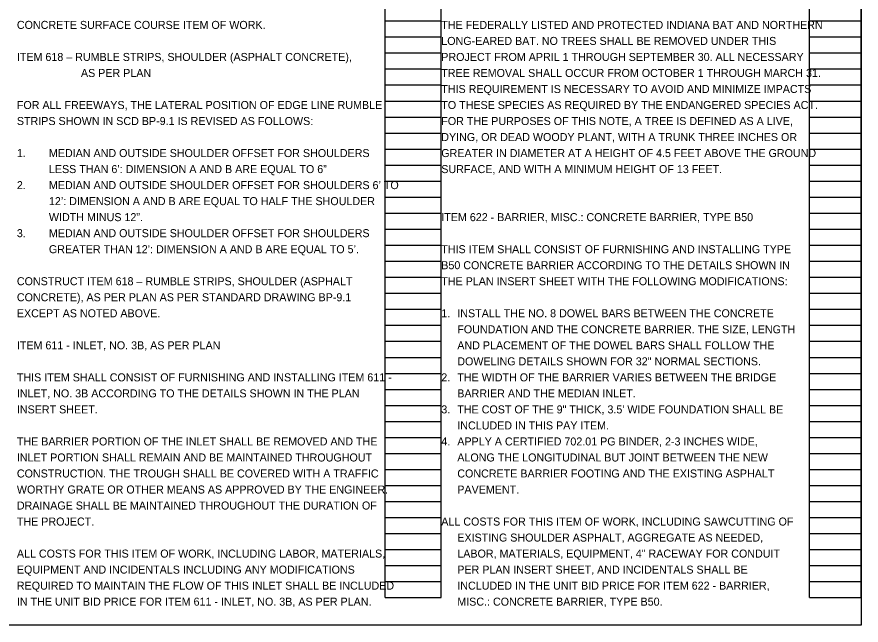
# Model space of a CAD drawing. Extents: x 0 to 2132911, y 0 to 658646.
# Drawn here: x 17.24 to 32, y 0.5 to 11.13 of the extents above; entities that cross this region are included whole.
import ezdxf

# ---------------------------------------------------------------- set-up
doc = ezdxf.new("R2010")
doc.units = 0
for name, color, linetype in [('SC_Scratch1', 7, 'Continuous'), ('SH_Data', 7, 'Continuous'), ('SH_Text', 7, 'Continuous')]:
    doc.layers.add(name, color=color, linetype=linetype)

msp = doc.modelspace()

# ---------------------------------------------------------------- linework, layer by layer
at = {"layer": 'SC_Scratch1'}
msp.add_lwpolyline([(1.5, 21.5), (32, 21.5), (32, 0.5), (1.5, 0.5)], close=True, dxfattribs=at)
at = {"layer": 'SH_Data'}
for p, q in [((23.68, 0.98), (23.68, 21.14)), ((24.66, 0.98), (24.66, 21.14)), ((31.1, 0.98), (31.1, 21.14)), ((32, 0.98), (32, 21.14)), ((23.68, 11.06), (24.66, 11.06)), ((31.1, 11.06), (32, 11.06)), ((23.68, 10.78), (24.66, 10.78)), ((31.1, 10.78), (32, 10.78)), ((23.68, 10.5), (24.66, 10.5)), ((31.1, 10.5), (32, 10.5)), ((23.68, 10.22), (24.66, 10.22)), ((31.1, 10.22), (32, 10.22)), ((23.68, 9.94), (24.66, 9.94)), ((31.1, 9.94), (32, 9.94)), ((23.68, 9.66), (24.66, 9.66)), ((31.1, 9.66), (32, 9.66)), ((23.68, 9.38), (24.66, 9.38)), ((31.1, 9.38), (32, 9.38)), ((23.68, 9.1), (24.66, 9.1)), ((31.1, 9.1), (32, 9.1)), ((23.68, 8.82), (24.66, 8.82)), ((31.1, 8.82), (32, 8.82)), ((23.68, 8.54), (24.66, 8.54)), ((31.1, 8.54), (32, 8.54)), ((23.68, 8.26), (24.66, 8.26)), ((31.1, 8.26), (32, 8.26)), ((23.68, 7.98), (24.66, 7.98)), ((31.1, 7.98), (32, 7.98)), ((23.68, 7.7), (24.66, 7.7)), ((31.1, 7.7), (32, 7.7)), ((23.68, 7.42), (24.66, 7.42)), ((31.1, 7.42), (32, 7.42)), ((23.68, 7.14), (24.66, 7.14)), ((31.1, 7.14), (32, 7.14)), ((23.68, 6.86), (24.66, 6.86)), ((31.1, 6.86), (32, 6.86)), ((23.68, 6.58), (24.66, 6.58)), ((31.1, 6.58), (32, 6.58)), ((23.68, 6.3), (24.66, 6.3)), ((31.1, 6.3), (32, 6.3)), ((23.68, 6.02), (24.66, 6.02)), ((31.1, 6.02), (32, 6.02)), ((23.68, 5.74), (24.66, 5.74)), ((31.1, 5.74), (32, 5.74)), ((23.68, 5.46), (24.66, 5.46)), ((31.1, 5.46), (32, 5.46)), ((23.68, 5.18), (24.66, 5.18)), ((31.1, 5.18), (32, 5.18)), ((23.68, 4.9), (24.66, 4.9)), ((31.1, 4.9), (32, 4.9)), ((23.68, 4.62), (24.66, 4.62)), ((31.1, 4.62), (32, 4.62)), ((23.68, 4.34), (24.66, 4.34)), ((31.1, 4.34), (32, 4.34)), ((23.68, 4.06), (24.66, 4.06)), ((31.1, 4.06), (32, 4.06)), ((23.68, 3.78), (24.66, 3.78)), ((31.1, 3.78), (32, 3.78)), ((23.68, 3.5), (24.66, 3.5)), ((31.1, 3.5), (32, 3.5)), ((23.68, 3.22), (24.66, 3.22)), ((31.1, 3.22), (32, 3.22)), ((23.68, 2.94), (24.66, 2.94)), ((31.1, 2.94), (32, 2.94)), ((23.68, 2.66), (24.66, 2.66)), ((31.1, 2.66), (32, 2.66)), ((23.68, 2.38), (24.66, 2.38)), ((31.1, 2.38), (32, 2.38)), ((23.68, 2.1), (24.66, 2.1)), ((31.1, 2.1), (32, 2.1)), ((23.68, 1.82), (24.66, 1.82)), ((31.1, 1.82), (32, 1.82)), ((23.68, 1.54), (24.66, 1.54)), ((31.1, 1.54), (32, 1.54)), ((23.68, 1.26), (24.66, 1.26)), ((31.1, 1.26), (32, 1.26)), ((23.68, 0.98), (24.66, 0.98)), ((31.1, 0.98), (32, 0.98))]:
    msp.add_line(p, q, dxfattribs=at)

# ---------------------------------------------------------------- texts
at = {"layer": 'SH_Text'}
for s, p in [('CONCRETE SURFACE COURSE ITEM OF WORK.', (17.24, 10.92)), ('THE FEDERALLY LISTED AND PROTECTED INDIANA BAT AND NORTHERN ', (24.66, 10.92)), ('LONG-EARED BAT. NO TREES SHALL BE REMOVED UNDER THIS ', (24.66, 10.64)), ('ITEM 618 – RUMBLE STRIPS, SHOULDER (ASPHALT CONCRETE),', (17.24, 10.36)), ('PROJECT FROM APRIL 1 THROUGH SEPTEMBER 30. ALL NECESSARY ', (24.66, 10.36)), ('AS PER PLAN', (18.36, 10.08)), ('TREE REMOVAL SHALL OCCUR FROM OCTOBER 1 THROUGH MARCH 31. ', (24.66, 10.08)), ('THIS REQUIREMENT IS NECESSARY TO AVOID AND MINIMIZE IMPACTS ', (24.66, 9.8)), ('FOR ALL FREEWAYS, THE LATERAL POSITION OF EDGE LINE RUMBLE ', (17.24, 9.52)), ('TO THESE SPECIES AS REQUIRED BY THE ENDANGERED SPECIES ACT. ', (24.66, 9.52)), ('STRIPS SHOWN IN SCD BP-9.1 IS REVISED AS FOLLOWS:', (17.24, 9.24)), ('FOR THE PURPOSES OF THIS NOTE, A TREE IS DEFINED AS A LIVE, ', (24.66, 9.24)), ('DYING, OR DEAD WOODY PLANT, WITH A TRUNK THREE INCHES OR ', (24.66, 8.96)), ('1.', (17.24, 8.68)), ('MEDIAN AND OUTSIDE SHOULDER OFFSET FOR SHOULDERS ', (17.8, 8.68)), ('GREATER IN DIAMETER AT A HEIGHT OF 4.5 FEET ABOVE THE GROUND ', (24.66, 8.68)), ('LESS THAN 6’: DIMENSION A AND B ARE EQUAL TO 6”', (17.8, 8.4)), ('SURFACE, AND WITH A MINIMUM HEIGHT OF 13 FEET.', (24.66, 8.4)), ('2.', (17.24, 8.12)), ('MEDIAN AND OUTSIDE SHOULDER OFFSET FOR SHOULDERS 6’ TO ', (17.8, 8.12)), ('12’: DIMENSION A AND B ARE EQUAL TO HALF THE SHOULDER ', (17.8, 7.84)), ('WIDTH MINUS 12”.', (17.8, 7.56)), ('ITEM 622 - BARRIER, MISC.: CONCRETE BARRIER, TYPE B50', (24.66, 7.56)), ('3.', (17.24, 7.28)), ('MEDIAN AND OUTSIDE SHOULDER OFFSET FOR SHOULDERS ', (17.8, 7.28)), ('GREATER THAN 12’: DIMENSION A AND B ARE EQUAL TO 5’.', (17.8, 7)), ('THIS ITEM SHALL CONSIST OF FURNISHING AND INSTALLING TYPE ', (24.66, 7)), ('B50 CONCRETE BARRIER ACCORDING TO THE DETAILS SHOWN IN ', (24.66, 6.72)), ('CONSTRUCT ITEM 618 – RUMBLE STRIPS, SHOULDER (ASPHALT ', (17.24, 6.44)), ('THE PLAN INSERT SHEET WITH THE FOLLOWING MODIFICATIONS:', (24.66, 6.44)), ('CONCRETE), AS PER PLAN AS PER STANDARD DRAWING BP-9.1 ', (17.24, 6.16)), ('EXCEPT AS NOTED ABOVE.', (17.24, 5.88)), ('1.', (24.66, 5.88)), ('INSTALL THE NO. 8 DOWEL BARS BETWEEN THE CONCRETE ', (24.94, 5.88)), ('FOUNDATION AND THE CONCRETE BARRIER. THE SIZE, LENGTH ', (24.94, 5.6)), ('ITEM 611 - INLET, NO. 3B, AS PER PLAN', (17.24, 5.32)), ('AND PLACEMENT OF THE DOWEL BARS SHALL FOLLOW THE ', (24.94, 5.32)), ('DOWELING DETAILS SHOWN FOR 32" NORMAL SECTIONS.', (24.94, 5.04)), ('THIS ITEM SHALL CONSIST OF FURNISHING AND INSTALLING ITEM 611 - ', (17.24, 4.76)), ('2.', (24.66, 4.76)), ('THE WIDTH OF THE BARRIER VARIES BETWEEN THE BRIDGE ', (24.94, 4.76)), ('INLET, NO. 3B ACCORDING TO THE DETAILS SHOWN IN THE PLAN ', (17.24, 4.48)), ('BARRIER AND THE MEDIAN INLET.', (24.94, 4.48)), ('INSERT SHEET.', (17.24, 4.2)), ('3.', (24.66, 4.2)), ('THE COST OF THE 9" THICK, 3.5\' WIDE FOUNDATION SHALL BE ', (24.94, 4.2)), ('INCLUDED IN THIS PAY ITEM.', (24.94, 3.92)), ('THE BARRIER PORTION OF THE INLET SHALL BE REMOVED AND THE ', (17.24, 3.64)), ('4.', (24.66, 3.64)), ('APPLY A CERTIFIED 702.01 PG BINDER, 2-3 INCHES WIDE, ', (24.94, 3.64)), ('INLET PORTION SHALL REMAIN AND BE MAINTAINED THROUGHOUT ', (17.24, 3.36)), ('ALONG THE LONGITUDINAL BUT JOINT BETWEEN THE NEW ', (24.94, 3.36)), ('CONSTRUCTION. THE TROUGH SHALL BE COVERED WITH A TRAFFIC ', (17.24, 3.08)), ('CONCRETE BARRIER FOOTING AND THE EXISTING ASPHALT ', (24.94, 3.08)), ('WORTHY GRATE OR OTHER MEANS AS APPROVED BY THE ENGINEER.', (17.24, 2.8)), ('PAVEMENT.', (24.94, 2.8)), ('DRAINAGE SHALL BE MAINTAINED THROUGHOUT THE DURATION OF ', (17.24, 2.52)), ('THE PROJECT.', (17.24, 2.24)), ('ALL COSTS FOR THIS ITEM OF WORK, INCLUDING SAWCUTTING OF ', (24.66, 2.24)), ('EXISTING SHOULDER ASPHALT, AGGREGATE AS NEEDED, ', (24.94, 1.96)), ('ALL COSTS FOR THIS ITEM OF WORK, INCLUDING LABOR, MATERIALS, ', (17.24, 1.68)), ('LABOR, MATERIALS, EQUIPMENT, 4" RACEWAY FOR CONDUIT ', (24.94, 1.68)), ('EQUIPMENT AND INCIDENTALS INCLUDING ANY MODIFICATIONS ', (17.24, 1.4)), ('PER PLAN INSERT SHEET, AND INCIDENTALS SHALL BE ', (24.94, 1.4)), ('REQUIRED TO MAINTAIN THE FLOW OF THIS INLET SHALL BE INCLUDED ', (17.24, 1.12)), ('INCLUDED IN THE UNIT BID PRICE FOR ITEM 622 - BARRIER, ', (24.94, 1.12)), ('IN THE UNIT BID PRICE FOR ITEM 611 - INLET, NO. 3B, AS PER PLAN.', (17.24, 0.84)), ('MISC.: CONCRETE BARRIER, TYPE B50.', (24.94, 0.84))]:
    msp.add_text(s, height=0.14, dxfattribs=at).set_placement(p)

doc.saveas('drawing.dxf')
